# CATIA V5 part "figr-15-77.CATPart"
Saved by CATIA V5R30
Part number: Part1
Bounding box of the stored display mesh (mm): x -59.264 to 75.079, y -54.323 to 58.486, z 0 to 41.762
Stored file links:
  D:\PROJECTS\CATIA V56R 2020\Resources\Parts File\c15_catia_v5_6r2020_prt\figr-15-77.CATPart
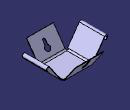
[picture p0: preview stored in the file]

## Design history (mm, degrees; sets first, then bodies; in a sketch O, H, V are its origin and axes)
SheetMetalParameters1: Thickness 1, BendRadius 5, KFactor 0.5 {= log(min(100,max(20*SheetMetalParameters1.BendRadius,SheetMetalParameters1.Thickness)/SheetMetalParameters1.Thickness))/log(100)/2}, ReliefRadialLength 1, ReliefAxialLength 2, MinimumBendRadius 0
Body1 (main body)
  Sketch1 on xy-plane, origin (0, 0, 0), H (1, 0, 0), V (0, 1, 0)
    line L1 (-24.5181, 30.1968) -> (40.3332, 30.1968)
    line L2 (40.3332, 30.1968) -> (40.3332, -26.0343)
    line L3 (40.3332, -26.0343) -> (-24.5181, -26.0343)
    line L4 (-24.5181, -26.0343) -> (-24.5181, 30.1968)
    horizontal: L1 H, L3 H
    vertical: L2 V, L4 V
  Wall1: Thickness 1, Profile Sketch1
  d_NewWallOnEdge1: NewWallOnEdge_Edge edge [face of Wall1 | face of Wall1], NewWallOnEdge_Length 40.2311, NewWallOnEdge_HeightLimitOffset 0, NewWallOnEdge_WidthOffset1 0, NewWallOnEdge_WidthOffset2 0, NewWallOnEdge_Angle 125, NewWallOnEdge_BendRadiusValue 5 {= SheetMetalParameters1.BendRadius}, NewWallOnEdge_BendTable SheetMetalParameters1, KFacteur 0.5 {= log(min(100,max(20*d_NewWallOnEdge1.Radius,SheetMetalParameters1.Thickness)/SheetMetalParameters1.Thickness))/log(100)/2}
  d_NewWallOnEdge2: NewWallOnEdge_Edge edge [face of Wall1 | face of Wall1], NewWallOnEdge_Length 40.2311, NewWallOnEdge_HeightLimitOffset 0, NewWallOnEdge_WidthOffset1 0, NewWallOnEdge_WidthOffset2 0, NewWallOnEdge_Angle 125, NewWallOnEdge_BendRadiusValue 5 {= SheetMetalParameters1.BendRadius}, NewWallOnEdge_BendTable SheetMetalParameters1, KFacteur 0.5 {= log(min(100,max(20*d_NewWallOnEdge2.Radius,SheetMetalParameters1.Thickness)/SheetMetalParameters1.Thickness))/log(100)/2}
  d_NewWallOnEdge3: NewWallOnEdge_Edge edge [face of Wall1 | face of Wall1], NewWallOnEdge_Length 40.2311, NewWallOnEdge_HeightLimitOffset 0, NewWallOnEdge_WidthOffset1 0, NewWallOnEdge_WidthOffset2 0, NewWallOnEdge_Angle 125, NewWallOnEdge_BendRadiusValue 5 {= SheetMetalParameters1.BendRadius}, NewWallOnEdge_BendTable SheetMetalParameters1, KFacteur 0.5 {= log(min(100,max(20*d_NewWallOnEdge3.Radius,SheetMetalParameters1.Thickness)/SheetMetalParameters1.Thickness))/log(100)/2}
  d_NewWallOnEdge4: NewWallOnEdge_Edge edge [face of Wall1 | face of Wall1], NewWallOnEdge_Length 40.2311, NewWallOnEdge_HeightLimitOffset 0, NewWallOnEdge_WidthOffset1 0, NewWallOnEdge_WidthOffset2 0, NewWallOnEdge_Angle 125, NewWallOnEdge_BendRadiusValue 5 {= SheetMetalParameters1.BendRadius}, NewWallOnEdge_BendTable SheetMetalParameters1, KFacteur 0.5 {= log(min(100,max(20*d_NewWallOnEdge4.Radius,SheetMetalParameters1.Thickness)/SheetMetalParameters1.Thickness))/log(100)/2}
  Sketch2 on face of d_NewWallOnEdge4, origin (0, -16.9994, -11.9031), H (-1, 0, 0), V (0, -0.5736, 0.8192)
    construction line L1 (-8.3417, 33.0355) -> (-8.3417, 47.6528)
    line L2 (-5.6402, 47.6528) -> (-5.6402, 38.4491)
    line L3 (-11.0431, 38.4491) -> (-11.0431, 47.6528)
    arc A1 centre (-8.3417, 33.0355) radius 6.0503 from (-5.6402, 38.4491) to (-11.0431, 38.4491) cw
    arc A2 centre (-8.3417, 47.6528) radius 2.7015 from (-11.0431, 47.6528) to (-5.6402, 47.6528) cw
    radius A1 = 6.0503
    radius A2 = 2.7015
    vertical: L1 V
    tangency: A2 L2, A2 L3
    parallelism: L2 L3, L2 L1
  CutOut1: Direction Sketch2, EndLimit through (limit type 3), Orientation false, Profile Sketch2, StartLimit through (limit type 2)
  Sketch3 on face of d_NewWallOnEdge2, origin (0, 19.7925, -13.8589), H (1, 0, 0), V (0, 0.5736, 0.8192)
    construction line L1 (6.0153, 41.1403) -> (6.0153, 57.8706)
    line L2 (8.7383, 57.8706) -> (8.7383, 46.3808)
    line L3 (3.2923, 46.3808) -> (3.2923, 57.8706)
    arc A1 centre (6.0153, 41.1403) radius 5.9058 from (8.7383, 46.3808) to (3.2923, 46.3808) cw
    arc A2 centre (6.0153, 57.8706) radius 2.723 from (3.2923, 57.8706) to (8.7383, 57.8706) cw
    radius A1 = 5.9058
    radius A2 = 2.723
    vertical: L1 V
    tangency: A2 L2, A2 L3
    parallelism: L2 L3, L2 L1
  CutOut2: Direction Sketch3, EndLimit through (limit type 3), Orientation true, Profile Sketch3, StartLimit through (limit type 2)
  Flange1: Angle 90, Length 5, Radius 3, KFacteur 0.444538 {= log(min(100,max(20*Flange1.Radius,SheetMetalParameters1.Thickness)/SheetMetalParameters1.Thickness))/log(100)/2}, Guide edge [face of d_NewWallOnEdge1 | face of d_NewWallOnEdge1]
  Flange2: Angle 90, Length 5, Radius 3, KFacteur 0.444538 {= log(min(100,max(20*Flange2.Radius,SheetMetalParameters1.Thickness)/SheetMetalParameters1.Thickness))/log(100)/2}, Guide edge [face of d_NewWallOnEdge3 | face of d_NewWallOnEdge3]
